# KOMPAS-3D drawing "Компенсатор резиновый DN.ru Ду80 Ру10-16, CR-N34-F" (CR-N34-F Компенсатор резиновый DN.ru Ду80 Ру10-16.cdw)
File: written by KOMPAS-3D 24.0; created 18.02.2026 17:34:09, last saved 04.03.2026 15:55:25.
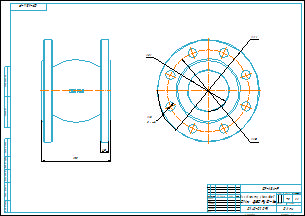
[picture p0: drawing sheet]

Document properties: Типовые: Типовые; Автор: DN.RU; Форматы листов документа: A2; Полное имя файла: CR-N34-F Компенсатор резиновый DN.ru Ду80 Ру10-16.m3d; Масса: 7.5; Наименование: Компенсатор резиновый DN.ru Ду80 Ру10-16; Количество листов документа: 1; Комментарий: D140-02091; Примечание: D140-02091

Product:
- Body: Твердое тело2  | qty 1
    Масса: 10.337867
- Part/product: Компенсатор резиновый DN.ru Ду80 Ру10-16  | designation CR-N34-F
    Масса: 7.5
    Раздел спецификации: Прочие изделия
    Комментарий: D140-02091
    Примечание: D140-02091
    additional columns: Типовые

Views: Вид 1, Спереди, Проекционный вид 2
Referenced files in E:\Работа\Зайцев\CR-N34-F Компенсатор резиновый DN.ru ДУ25-300 Ру10-16\DN80_PN10-16\: CR-N34-F Компенсатор резиновый DN.ru Ду80 Ру10-16.m3d
Referenced files in E:\Работа\Зайцев\Для компаса\: чертеж DN.ru А3.cdt
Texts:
  CR-N34-F
  чертеж DN.ru А3.cdt
  Компенсатор резиновый
  DN.ru Ду80 Ру10-16
  Твердое тело2
  Компенсатор резиновый DN.ru Ду80 Ру10-16
  CR-N34-F Компенсатор резиновый DN.ru Ду80 Ру10-16
Dimensions and other numbers on the sheet: 0; 3; 2; 4; 135; 16; 200; 160; 80; 18; 8 отв.; 1:1; 1; 7,5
